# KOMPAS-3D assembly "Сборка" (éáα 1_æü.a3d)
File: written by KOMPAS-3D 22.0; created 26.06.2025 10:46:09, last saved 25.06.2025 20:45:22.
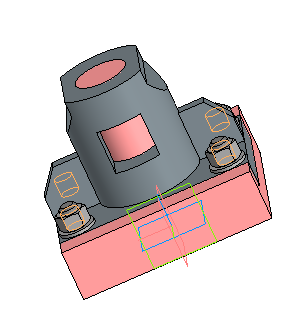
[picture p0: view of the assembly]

Document properties: Автор: Helen; Полное имя файла: D:\MY\WORK\MPEI\ППЭ_2025-2026\Варианты\Вар 1 СБ\Вар 1_СБ.a3d

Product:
- Component [detail]: Основание  | designation Вариант 1  | qty 1  | Масса: 5.217114; source file: Основание _ Вариант 1.m3d
- Component [detail]: Nodes  | qty 1  | Масса: 8.574337; source file: Корпус вар1.m3d
- Component [detail]: Сборка  | qty 4  | Масса: 0.008612; source file: Шайба 14.m3d
- Component [detail]: Сборка  | qty 4  | Масса: 0.02533; source file: Гайка М14.m3d
- Component [detail]: Сборка  | qty 4  | Масса: 0.091885; source file: Болт М14х60.m3d
- Part/product: Сборка
    Масса: 14.294757

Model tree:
1. Массив по сетке:1  (with: Элемент выдавливания:1, Операция без истории:1, Операция без истории:2, Элемент выдавливания:4)  (4 pattern instances)
     Шаг 1 = 120; Угол раствора = 90; Шаг 2 = 70

Referenced files in D:\MY\WORK\MPEI\ППЭ_2025-2026\Варианты\Вар 1 СБ\: Основание _ Вариант 1.m3d, Корпус вар1.m3d, Шайба 14.m3d, Гайка М14.m3d, Болт М14х60.m3d
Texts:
  Вариант 1 Основание
  Сборка (1)
  Сборка (2)
  Сборка (3)
  Сборка (4)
